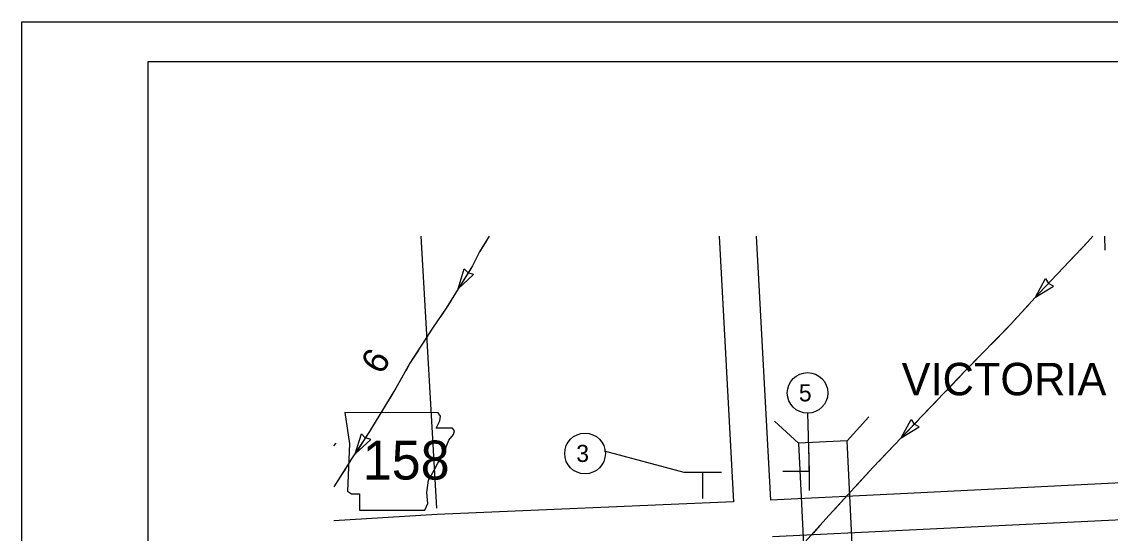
# Model space of a CAD drawing. Extents: x 9792 to 14027, y 9583 to 10649.
# Drawn here: x 9792 to 10326, y 10398 to 10649 of the extents above; entities that cross this region are included whole.
import ezdxf

# ---------------------------------------------------------------- set-up
doc = ezdxf.new("R2010")
doc.units = 0
for name, color, linetype in [('Default', 7, 'Continuous'), ('R_Border', 7, 'Continuous'), ('R_Border Notes', 7, 'Continuous'), ('R_MOT', 7, 'Continuous'), ('R_No Plot', 7, 'Continuous')]:
    doc.layers.add(name, color=color, linetype=linetype)

msp = doc.modelspace()

# ---------------------------------------------------------------- linework, layer by layer
at = {"layer": 'Default'}
for p, q in [((10006.44, 10518.2), (10009.42, 10528.1)), ((10006.44, 10518.2), (10013.97, 10525.28)), ((10009.42, 10528.1), (10011.31, 10526.1)), ((10013.97, 10525.28), (10011.34, 10526.08)), ((10289.7, 10514.17), (10294.62, 10523.27)), ((10289.7, 10514.17), (10298.51, 10519.59)), ((10294.62, 10523.27), (10296.07, 10520.92)), ((10298.51, 10519.59), (10296.09, 10520.9)), ((10197.23, 10443.68), (10207.92, 10455.47)), ((10223.82, 10445.06), (10228.79, 10454.13)), ((10228.79, 10454.13), (10230.22, 10451.78)), ((10173.39, 10442.51), (10161.6, 10453.2)), ((10223.82, 10445.06), (10232.66, 10450.43)), ((10232.66, 10450.43), (10230.24, 10451.75)), ((9955.78, 10437.29), (9958.98, 10447.13)), ((9955.78, 10437.29), (9963.47, 10444.21)), ((9958.98, 10447.13), (9960.82, 10445.08)), ((9963.47, 10444.21), (9960.85, 10445.06)), ((10197.23, 10443.68), (10173.39, 10442.51)), ((10200.73, 10372.15), (10197.23, 10443.68)), ((9945.36, 10441.14), (9946.58, 10442.53)), ((10173.39, 10442.51), (10176.22, 10384.58))]:
    msp.add_line(p, q, dxfattribs=at)
for points in [[(10021.68, 10544.04), (10016.83, 10536.41), (10013.48, 10529.58), (10000.55, 10508.68), (9993.81, 10498.97), (9982.66, 10481.68), (9978.64, 10474.44), (9975.83, 10469.51), (9962.86, 10448.19), (9954.12, 10434.74), (9948.49, 10425.89), (9945.36, 10420.99)], [(9988.13, 10544.04), (9995.72, 10410.55)], [(10020.51, 10542.2), (10016.83, 10536.41), (10014.59, 10531.85)], [(10317.79, 10544.04), (10315.2, 10541.1), (10291.61, 10516.19), (10289.54, 10513.91), (10277.87, 10501.13), (10255.36, 10478.07), (10209.88, 10430.47), (10186.88, 10405.41), (10154.77, 10369.75), (10120.4, 10333.38)], [(10134.49, 10544.04), (10141.54, 10413.66)], [(10152.6, 10544.04), (10159.61, 10414.49)], [(10317.79, 10544.04), (10315.2, 10541.1), (10311.58, 10537.28)], [(10323.53, 10544.04), (10323.84, 10537.17)], [(10308.85, 10534.4), (10300.64, 10525.73)], [(10012.72, 10528.35), (10006.44, 10518.2)], [(10297.91, 10522.84), (10291.61, 10516.19), (10289.74, 10514.13)], [(10004.34, 10514.81), (10001.2, 10509.74)], [(10001.2, 10509.74), (10000.55, 10508.68), (9997.86, 10504.8)], [(10287.06, 10511.19), (10283.04, 10506.78)], [(10283.04, 10506.78), (10279.01, 10502.38)], [(9995.59, 10501.53), (9993.81, 10498.97), (9989.03, 10491.56)], [(10276.27, 10499.49), (10267.93, 10490.95)], [(9986.87, 10488.21), (9982.66, 10481.68), (9980.64, 10478.04)], [(10265.16, 10488.1), (10256.82, 10479.56)], [(10254.05, 10476.7), (10245.81, 10468.07)], [(9978.71, 10474.56), (9978.64, 10474.44), (9975.83, 10469.51), (9972.65, 10464.28)], [(10243.06, 10465.19), (10234.81, 10456.56)], [(9970.58, 10460.88), (9964.38, 10450.68)], [(10232.07, 10453.69), (10223.82, 10445.06)], [(9962.28, 10447.3), (9955.78, 10437.29)], [(10221.07, 10442.18), (10216.95, 10437.86)], [(9953.62, 10433.95), (9950.41, 10428.92)], [(10216.95, 10437.86), (10212.83, 10433.55)], [(9950.41, 10428.92), (9948.49, 10425.89), (9947.21, 10423.88)], [(10490.11, 10429.57), (10348.34, 10423.75), (10226.94, 10417.78), (10159.61, 10414.49)], [(10210.08, 10430.67), (10209.88, 10430.47), (10202, 10421.88)], [(10199.31, 10418.95), (10191.24, 10410.16)], [(10141.54, 10413.66), (9996.05, 10407.52), (9945.36, 10404.36)], [(10490.85, 10411.5), (10349.15, 10405.68), (10227.83, 10399.71), (10160.59, 10396.43)], [(10183.82, 10402.02), (10180.54, 10398.37)]]:
    msp.add_lwpolyline(points, dxfattribs=at)
msp.add_lwpolyline([(9950.78, 10457.47), (9953.07, 10442.17), (9952.05, 10418.96), (9954.09, 10417.69), (9957.92, 10417.69), (9957.92, 10409.53), (9990.04, 10409.53), (9991.57, 10412.85), (9991.06, 10418.2), (9991.83, 10424.32), (9994.63, 10429.16), (9996.42, 10432.73), (9998.97, 10436.56), (10000.5, 10440.64), (10001.77, 10443.95), (10004.07, 10446.76), (10004.58, 10448.54), (10003.56, 10449.82), (9995.65, 10449.82), (9997.44, 10453.39), (9997.69, 10455.68), (9996.64, 10457.44)], close=True, dxfattribs=at)
at = {"layer": 'R_Border'}
for p, q in [((9854.26, 10629.85), (11435.16, 10629.85)), ((9854.26, 9602.55), (9854.26, 10629.85))]:
    msp.add_line(p, q, dxfattribs=at)
at = {"layer": 'R_Border Notes'}
for p, q in [((10177.89, 10457.16), (10178.61, 10428.57)), ((10078.09, 10438.8), (10117.08, 10428.23))]:
    msp.add_line(p, q, dxfattribs=at)
for centre in [(10177.89, 10467.14), (10068.65, 10437.41)]:
    msp.add_circle(centre, 9.97, dxfattribs=at)
at = {"layer": 'R_MOT'}
for p, q in [((10178.57, 10437.79), (10178.66, 10419.26)), ((10117.08, 10428.23), (10135.61, 10428.31)), ((10126.31, 10428.27), (10126.36, 10415.35)), ((10178.61, 10428.57), (10165.69, 10428.51))]:
    msp.add_line(p, q, dxfattribs=at)
at = {"layer": 'R_No Plot'}
msp.add_line((9792.26, 10649.32), (11458.93, 10649.32), dxfattribs=at)
for points in [[(9792.23, 10649.32), (11458.93, 10649.32), (11458.93, 9582.63), (9792.23, 9582.63)], [(11023.86, 10629.85), (11023.86, 10580.45), (11202.52, 10580.45), (11202.52, 10565.85), (11318.52, 10565.85), (11318.52, 10444.19), (11435.16, 10444.19), (11435.16, 9602.55), (9854.26, 9602.55), (9854.26, 10629.85)]]:
    msp.add_lwpolyline(points, close=True, dxfattribs=at)

# ---------------------------------------------------------------- texts
at = {"layer": 'Default'}
msp.add_text('6', height=12.73, rotation=58.5548, dxfattribs=at).set_placement((9968.76, 10475.57))
for s, height, p in [('VICTORIA', 15.915, (10224.03, 10465.99)), ('158', 19.098, (9959.58, 10424.63))]:
    msp.add_text(s, height=height, dxfattribs=at).set_placement(p)
at = {"layer": 'R_Border Notes'}
for s, p in [('5', (10173.61, 10462.99)), ('3', (10064.36, 10433.27))]:
    msp.add_text(s, height=8.4, dxfattribs=at).set_placement(p)

doc.saveas('drawing.dxf')
